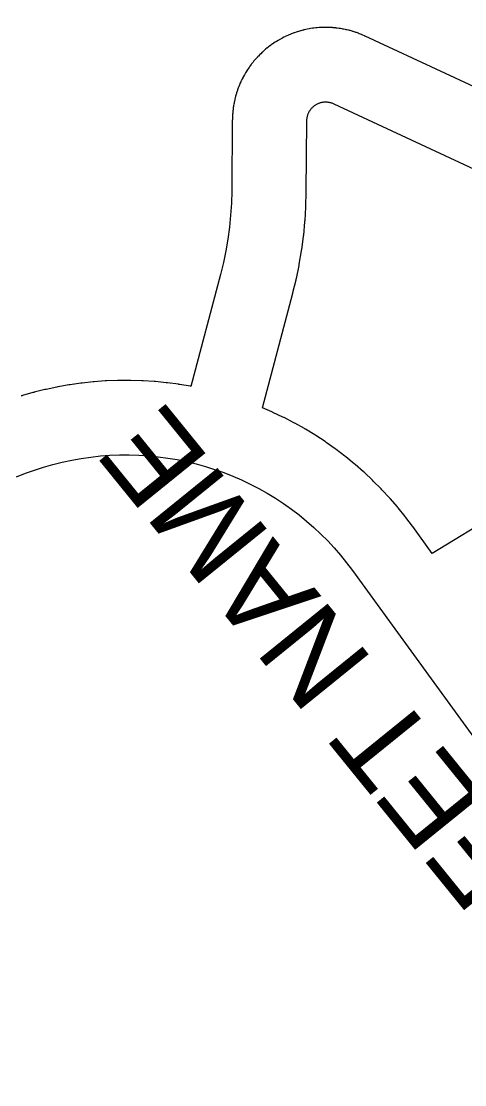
# Model space of a CAD drawing. Extents: x 599744 to 600217, y 4827560 to 4828065.
# Drawn here: x 600007.45 to 600011.01, y 4827989.68 to 4827998.23 of the extents above; entities that cross this region are included whole.
import ezdxf

# ---------------------------------------------------------------- set-up
doc = ezdxf.new("R2010")
doc.units = 0
doc.layers.add('G-ANNO-KEYP', color=7, linetype='Continuous')

msp = doc.modelspace()

# ---------------------------------------------------------------- linework, layer by layer
at = {"layer": 'G-ANNO-KEYP'}
for points in [[(600009.8996, 4827998.1809), (600009.898, 4827998.1814), (600009.882, 4827998.1813), (600009.8723, 4827998.1806), (600009.8712, 4827998.181), (600009.8551, 4827998.1802), (600009.8452, 4827998.1794), (600009.8446, 4827998.1796), (600009.8286, 4827998.1783), (600009.818, 4827998.1772), (600009.8179, 4827998.1772), (600009.802, 4827998.1753), (600009.8, 4827998.1751), (600009.7913, 4827998.1739), (600009.7755, 4827998.1714), (600009.7751, 4827998.1712), (600009.7651, 4827998.1696), (600009.7493, 4827998.1666), (600009.7485, 4827998.1661), (600009.7387, 4827998.1644), (600009.7231, 4827998.1609), (600009.7219, 4827998.1601), (600009.7128, 4827998.1583), (600009.6973, 4827998.1542), (600009.6957, 4827998.1531), (600009.6871, 4827998.1513), (600009.6717, 4827998.1466), (600009.6696, 4827998.1452), (600009.6613, 4827998.1433), (600009.6461, 4827998.138), (600009.6437, 4827998.1363), (600009.6362, 4827998.1344), (600009.6212, 4827998.1286), (600009.6184, 4827998.1265), (600009.6114, 4827998.1246), (600009.5966, 4827998.1184), (600009.5934, 4827998.1159), (600009.5869, 4827998.114), (600009.5724, 4827998.1072), (600009.5688, 4827998.1043), (600009.5626, 4827998.1025), (600009.5484, 4827998.0951), (600009.5444, 4827998.0919), (600009.5389, 4827998.09), (600009.5249, 4827998.0822), (600009.5207, 4827998.0786), (600009.5158, 4827998.0769), (600009.502, 4827998.0686), (600009.4975, 4827998.0645), (600009.493, 4827998.0629), (600009.4796, 4827998.0541), (600009.4747, 4827998.0496)], [(600012.1499, 4827997.2096), (600010.214, 4827998.1114), (600010.2124, 4827998.1116), (600010.2091, 4827998.1136), (600010.1944, 4827998.1201), (600010.191, 4827998.1206), (600010.1846, 4827998.1243), (600010.1697, 4827998.1303), (600010.1657, 4827998.1308), (600010.1598, 4827998.134), (600010.1447, 4827998.1395), (600010.14, 4827998.14), (600010.1343, 4827998.1431), (600010.119, 4827998.148), (600010.1141, 4827998.1484), (600010.1092, 4827998.1509), (600010.0937, 4827998.1553), (600010.0881, 4827998.1557), (600010.0833, 4827998.1581), (600010.0677, 4827998.1619), (600010.0616, 4827998.1622), (600010.0572, 4827998.1642), (600010.0415, 4827998.1675), (600010.0348, 4827998.1678), (600010.0309, 4827998.1695), (600010.0151, 4827998.1722), (600010.0081, 4827998.1723), (600010.0047, 4827998.1737), (600009.9888, 4827998.1759), (600009.981, 4827998.1759), (600009.978, 4827998.1771), (600009.962, 4827998.1787), (600009.9539, 4827998.1785), (600009.9513, 4827998.1795), (600009.9353, 4827998.1805), (600009.9269, 4827998.1802), (600009.9249, 4827998.1809), (600009.9088, 4827998.1814), (600009.8996, 4827998.1809)], [(600009.4747, 4827998.0496), (600009.4707, 4827998.048), (600009.4576, 4827998.0387), (600009.4524, 4827998.0338), (600009.449, 4827998.0324), (600009.4362, 4827998.0226), (600009.4309, 4827998.0174), (600009.4279, 4827998.0161), (600009.4155, 4827998.0059), (600009.4098, 4827998), (600009.4073, 4827997.9989), (600009.3953, 4827997.9883), (600009.3893, 4827997.9819), (600009.3873, 4827997.981), (600009.3757, 4827997.9699), (600009.3697, 4827997.9632), (600009.3682, 4827997.9625), (600009.3569, 4827997.9511), (600009.3506, 4827997.9438), (600009.3495, 4827997.9432), (600009.3387, 4827997.9314), (600009.3323, 4827997.9238), (600009.3318, 4827997.9235), (600009.3214, 4827997.9113), (600009.3145, 4827997.9029), (600009.3145, 4827997.9028), (600009.3045, 4827997.8902), (600009.3032, 4827997.8886), (600009.2982, 4827997.8819), (600009.2887, 4827997.869), (600009.2886, 4827997.8686), (600009.2824, 4827997.86), (600009.2733, 4827997.8468), (600009.2731, 4827997.8459), (600009.2675, 4827997.8379), (600009.259, 4827997.8243), (600009.2586, 4827997.8229), (600009.2535, 4827997.8153), (600009.2455, 4827997.8014), (600009.2451, 4827997.7994), (600009.2402, 4827997.7919), (600009.2326, 4827997.7777), (600009.2322, 4827997.7753), (600009.2278, 4827997.7684), (600009.2208, 4827997.754), (600009.2203, 4827997.751), (600009.2162, 4827997.7441), (600009.2097, 4827997.7295), (600009.2091, 4827997.726), (600009.2056, 4827997.7198)], [(600009.2056, 4827997.7198), (600009.1995, 4827997.7049), (600009.199, 4827997.7008), (600009.1956, 4827997.6947), (600009.1902, 4827997.6796), (600009.1897, 4827997.6751), (600009.1868, 4827997.6697), (600009.1819, 4827997.6544), (600009.1814, 4827997.6493), (600009.1787, 4827997.644), (600009.1743, 4827997.6286), (600009.1739, 4827997.6231), (600009.1716, 4827997.6184), (600009.1678, 4827997.6028), (600009.1675, 4827997.5967), (600009.1655, 4827997.5923), (600009.1622, 4827997.5766), (600009.1619, 4827997.5701), (600009.1602, 4827997.5662), (600009.1575, 4827997.5504), (600009.1574, 4827997.5431), (600009.1559, 4827997.5396), (600009.1537, 4827997.5237), (600009.1537, 4827997.5161), (600009.1525, 4827997.5132), (600009.151, 4827997.4972), (600009.1511, 4827997.4892), (600009.1501, 4827997.4867), (600009.1491, 4827997.4707), (600009.1494, 4827997.4619), (600009.1486, 4827997.4598), (600009.1482, 4827997.4437), (600009.1484, 4827997.4394), (600009.1481, 4827997.4385), (600009.1432, 4827996.866), (600009.1406, 4827996.7677), (600009.1346, 4827996.6712), (600009.1253, 4827996.5758), (600009.1124, 4827996.4801), (600009.0962, 4827996.3852), (600009.0767, 4827996.2911), (600009.0532, 4827996.195), (600008.8156, 4827995.2952), (600008.8153, 4827995.2952), (600008.8116, 4827995.2968), (600008.725, 4827995.3116), (600008.7182, 4827995.3117), (600008.7149, 4827995.3131), (600008.6279, 4827995.3248), (600008.6205, 4827995.3249), (600008.6176, 4827995.326), (600008.5303, 4827995.3348)], [(600009.742, 4827996.8586), (600009.7469, 4827997.4309), (600009.7471, 4827997.4388), (600009.7474, 4827997.4441), (600009.748, 4827997.4495), (600009.7487, 4827997.4548), (600009.7495, 4827997.4598), (600009.7507, 4827997.4654), (600009.752, 4827997.4706), (600009.7535, 4827997.4759), (600009.755, 4827997.4807), (600009.7569, 4827997.486), (600009.7588, 4827997.4907), (600009.7611, 4827997.4957), (600009.7635, 4827997.5006), (600009.766, 4827997.5055), (600009.7685, 4827997.5096), (600009.7717, 4827997.5148), (600009.7745, 4827997.5189), (600009.7777, 4827997.5233), (600009.781, 4827997.5274), (600009.7845, 4827997.5316), (600009.7883, 4827997.5357), (600009.7919, 4827997.5394), (600009.7959, 4827997.5431), (600009.7997, 4827997.5466), (600009.8042, 4827997.5502), (600009.808, 4827997.5531), (600009.8127, 4827997.5565), (600009.8172, 4827997.5594), (600009.8218, 4827997.5622), (600009.8264, 4827997.5648), (600009.8312, 4827997.5672), (600009.836, 4827997.5695), (600009.8411, 4827997.5717), (600009.8458, 4827997.5735), (600009.8514, 4827997.5754), (600009.8561, 4827997.5768), (600009.8613, 4827997.5782), (600009.8666, 4827997.5794), (600009.872, 4827997.5804), (600009.8773, 4827997.5813), (600009.8826, 4827997.5819), (600009.888, 4827997.5823), (600009.8933, 4827997.5826), (600009.8987, 4827997.5826), (600009.904, 4827997.5825), (600009.9096, 4827997.5822), (600009.9148, 4827997.5817), (600009.9198, 4827997.581), (600009.9256, 4827997.58), (600009.9307, 4827997.5789)], [(600009.9307, 4827997.5789), (600009.9356, 4827997.5777), (600009.9412, 4827997.5762), (600009.9462, 4827997.5746), (600009.9511, 4827997.5728), (600009.9563, 4827997.5707), (600009.9635, 4827997.5675), (600011.8998, 4827996.6655)], [(600010.1268, 4827994.6744), (600010.0588, 4827994.73), (600010.0534, 4827994.7343), (600010.0507, 4827994.7363), (600009.9809, 4827994.7895), (600009.9807, 4827994.7895), (600009.9725, 4827994.7956), (600009.9009, 4827994.8463), (600009.9003, 4827994.8465), (600009.8924, 4827994.8521), (600009.819, 4827994.9003), (600009.818, 4827994.9006), (600009.8103, 4827994.9058), (600009.7353, 4827994.9515), (600009.7338, 4827994.9519), (600009.7265, 4827994.9567), (600009.65, 4827994.9998), (600009.6479, 4827995.0002), (600009.6409, 4827995.0047), (600009.563, 4827995.0451), (600009.5605, 4827995.0455), (600009.5537, 4827995.0497), (600009.4745, 4827995.0873), (600009.4714, 4827995.0878), (600009.4651, 4827995.0916), (600009.3898, 4827995.1243), (600009.6328, 4827996.0447), (600009.633, 4827996.0476), (600009.6341, 4827996.0499), (600009.6596, 4827996.1538), (600009.66, 4827996.1598), (600009.6619, 4827996.1642), (600009.6837, 4827996.2689), (600009.6839, 4827996.2755), (600009.6857, 4827996.2794), (600009.7036, 4827996.3848), (600009.7038, 4827996.3919), (600009.7052, 4827996.3953), (600009.7195, 4827996.5013), (600009.7195, 4827996.5089), (600009.7207, 4827996.5119), (600009.7311, 4827996.6183), (600009.731, 4827996.6264), (600009.732, 4827996.629), (600009.7386, 4827996.7357), (600009.7383, 4827996.7444), (600009.7391, 4827996.7464), (600009.7419, 4827996.8533), (600009.7417, 4827996.8577), (600009.742, 4827996.8586)], [(600008.5303, 4827995.3348), (600008.5225, 4827995.3347), (600008.52, 4827995.3356), (600008.4324, 4827995.3413), (600008.4242, 4827995.3411), (600008.4221, 4827995.3418), (600008.3344, 4827995.3445), (600008.3257, 4827995.3441), (600008.3241, 4827995.3447), (600008.2363, 4827995.3443), (600008.2271, 4827995.3437), (600008.226, 4827995.3441), (600008.1383, 4827995.3408), (600008.1287, 4827995.34), (600008.128, 4827995.3402), (600008.0404, 4827995.3338), (600008.0304, 4827995.3329), (600008.0302, 4827995.3329), (600007.9429, 4827995.3235), (600007.9379, 4827995.323), (600007.9327, 4827995.3223), (600007.8458, 4827995.3099), (600007.8456, 4827995.3098), (600007.8356, 4827995.3083), (600007.7491, 4827995.2929), (600007.7485, 4827995.2925), (600007.7391, 4827995.2909), (600007.6532, 4827995.2726), (600007.6522, 4827995.272), (600007.6431, 4827995.2703), (600007.558, 4827995.249), (600007.5566, 4827995.2481), (600007.548, 4827995.2464), (600007.4636, 4827995.2222), (600007.4619, 4827995.221), (600007.4538, 4827995.2192)], [(600007.4154, 4827994.5689), (600007.4869, 4827994.5977), (600007.5597, 4827994.6241), (600007.6338, 4827994.6481), (600007.7078, 4827994.6693), (600007.7832, 4827994.6881), (600007.859, 4827994.7043), (600007.9352, 4827994.7178), (600008.012, 4827994.7287), (600008.0888, 4827994.737), (600008.1663, 4827994.7426), (600008.2436, 4827994.7456), (600008.3212, 4827994.7458), (600008.3986, 4827994.7435), (600008.476, 4827994.7384), (600008.553, 4827994.7307), (600008.6297, 4827994.7204), (600008.7063, 4827994.7074), (600008.782, 4827994.6918), (600008.8573, 4827994.6736), (600008.932, 4827994.6528)], [(600008.932, 4827994.6528), (600009.0056, 4827994.6295), (600009.0789, 4827994.6035), (600009.1511, 4827994.5751), (600009.2218, 4827994.5444), (600009.2922, 4827994.511), (600009.3606, 4827994.4755), (600009.4282, 4827994.4375), (600009.4945, 4827994.3971), (600009.5592, 4827994.3546), (600009.6225, 4827994.3098), (600009.684, 4827994.263), (600009.744, 4827994.2139), (600009.8024, 4827994.1629), (600009.8589, 4827994.1098), (600009.9134, 4827994.055), (600009.9663, 4827993.998), (600010.0169, 4827993.9396), (600010.0656, 4827993.8793), (600010.1137, 4827993.8154), (600010.4309, 4827993.3783), (600010.4309, 4827993.3783), (600011.8849, 4827991.375)], [(600011.279, 4827994.2747), (600010.7532, 4827993.9537), (600010.5968, 4827994.1692), (600010.5944, 4827994.1716), (600010.5937, 4827994.1733), (600010.541, 4827994.2435), (600010.5359, 4827994.2486), (600010.5346, 4827994.2516), (600010.4795, 4827994.3199), (600010.474, 4827994.3253), (600010.4729, 4827994.3278), (600010.4154, 4827994.3941), (600010.4095, 4827994.3997), (600010.4085, 4827994.4018), (600010.3488, 4827994.4661), (600010.3424, 4827994.472), (600010.3416, 4827994.4736), (600010.2797, 4827994.5358), (600010.2729, 4827994.5418), (600010.2724, 4827994.543), (600010.2084, 4827994.603), (600010.2011, 4827994.6092), (600010.2007, 4827994.61), (600010.1347, 4827994.6678), (600010.127, 4827994.6742), (600010.1268, 4827994.6744)]]:
    msp.add_lwpolyline(points, dxfattribs=at)

# ---------------------------------------------------------------- texts
for s, rotation, p in [('STREET B', 337.62695, (600009.9971, 4827999.6776)), ('STREET NAME', 129.02565, (600012.7792, 4827990.0136))]:
    msp.add_text(s, height=0.7, rotation=rotation, dxfattribs=at).set_placement(p)

doc.saveas('drawing.dxf')
